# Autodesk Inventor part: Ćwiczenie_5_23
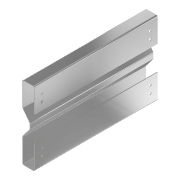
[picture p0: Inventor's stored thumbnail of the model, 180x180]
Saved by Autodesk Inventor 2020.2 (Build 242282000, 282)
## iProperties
Created: 2005-03
Part Number: Ćwiczenie_5_23
Document SubType Name: Modeling
Designer: F.Stasiak
Manufacturer: Standard
Standards Organization: Custom
Density: 7.1 g/cm^3
Material: Ogólny
Appearance: Chrom — polerowany
Manager: www.cadconsulting.pl
Company: Fabian Stasiak CAD Consulting
Author: F.Stasiak
Subject: Zbiór ćwiczeń. Autodesk Inventor 2020. Kurs podstawowy
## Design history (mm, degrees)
sketch "Szkic2"
  geometry: L1 (-10, 50)-(-10, 150); L2 (-10, 150)-(40, 150); L3 (40, 150)-(40, 50); L4 (40, 50)-(10, 10); L5 (10, 10)-(10, -10); L6 (10, -10)-(40, -50); L7 (40, -50)-(40, -150); L8 (40, -150)-(-10, -150); L9 (-10, -150)-(-10, -50); L10 (10, 0)-(-10, 0); L11 (-10, 50)-(-10, -50); L12 (37, 51)-(37, 147); L13 (37, 147)-(-7, 147); L14 (-7, 147)-(-7, 50); L15 (-7, 50)-(-7, -50); L16 (-7, -50)-(-7, -147); L17 (-7, -147)-(37, -147); L18 (37, -147)-(37, -51); L19 (37, -51)-(7, -11); L20 (7, -11)-(7, 11); L21 (7, 11)-(37, 51); L22 (-7, 50)-(-10, 50); L23 (-7, -50)-(-10, -50); 2 further points
  constraints: 46 end point, 9 parallel, 5 collinear, 5 perpendicular, 3 midpoint, 1 coincident, 1 vertical, 14 other
  dimensions: "d0" = 300 distance between parallel lines of L8 L2; "d1" = 50 distance of L7.end L8.end; "d2" = 30 distance between parallel lines of L7 L5; "d3" = 100 distance of L2.end L3.end; "d4" = 20 distance of L4.end L5.end; "d5" = 100 distance of L1.start L1.end; "d6" = 3 distance between parallel lines of L9 L16
extrude "Wyciągnięcie proste1" new body sketch "Szkic2" stored distance "d7" = 500; taper "d8" = 0 deg
fillet "Zaokrąglenie1" dims "d9" = 3
fillet "Zaokrąglenie2" dims "d10" = 6
hole "Otwór1" diameter "d14" = 10.5; stored, may be unused: countersink angle "d18" = 90 deg, drill point angle "d20" = 118 deg; dims "d12" = 30, "d13" = 30, "d15" = 6, "d16" = 4, "d17" = 2, "d19" = 8
pattern_linear "Szyk prostokątny1" dims "d23" = 30, "d26" = 440 (computed from d7)
mirror "Lustro1"
node "Bryła1"
node "Korpusy bryłowe"
node "Korpusy powierzchniowe"
